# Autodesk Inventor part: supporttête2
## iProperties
Created: 2002-09
Part Number: supporttête2
Material: Par défaut
Document SubType Name: Modélisation
Designer: Maison
Control State: 0
Master: False
Checked Out: False
Shininess: 20.0
Length Units: 11269
Angle Units: 11279
Time Units: 11290
Mass Units: 11283
Length Display Precision: 3
Angle Display Precision: 2
Density: 0.0
Volumn: 0.0
Area: 0.0
PropertySet Name: Model Information
Author: Maison
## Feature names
1. Extrusion1
2. Extrusion3
3. Extrusion4
4. Extrusion5
